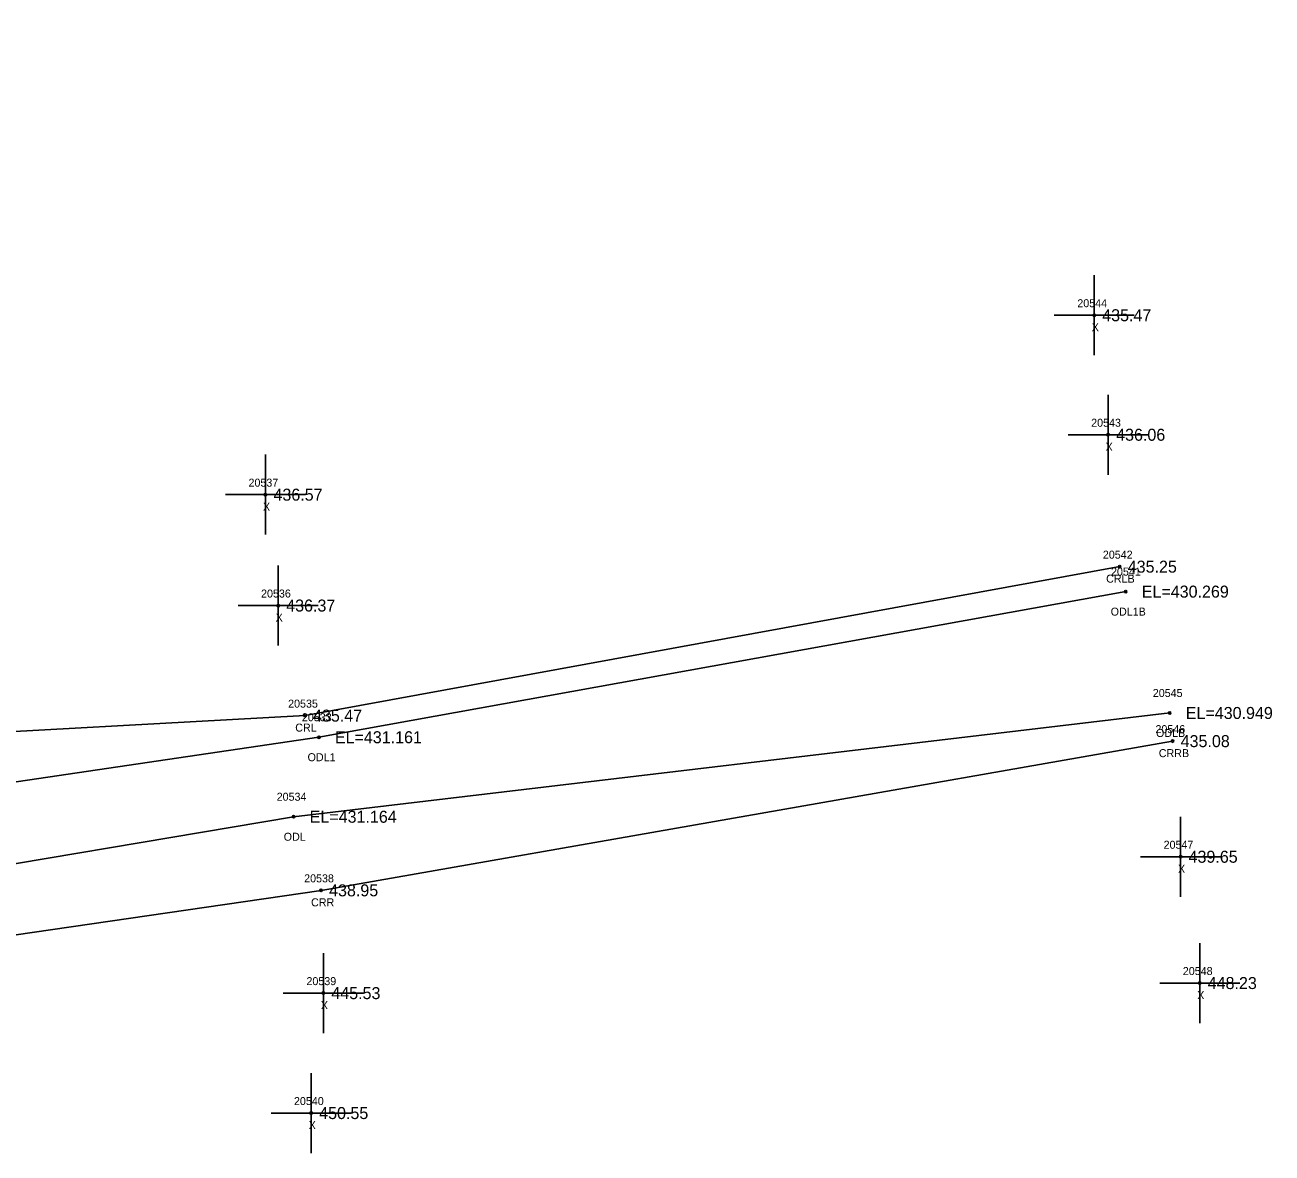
# Model space of a CAD drawing. Extents: x 1763022 to 1764007, y 824123 to 825394.
# Drawn here: x 1763783.3 to 1763939.1, y 824530.8 to 824671.8 of the extents above; entities that cross this region are included whole.
import ezdxf

# ---------------------------------------------------------------- set-up
doc = ezdxf.new("R2010")
doc.units = 0
for name, color, linetype in [('RD_EX_H2O', 7, 'Continuous'), ('RD_EX_H2O_txCode', 7, 'Continuous'), ('RD_EX_Misc', 7, 'Continuous'), ('RD_EX_Misc_txCode', 7, 'Continuous'), ('RD_EX_TX_H2O_ELEV', 7, 'Continuous'), ('RD_EX_TX_Misc_ELEV', 7, 'Continuous'), ('RD_SMD_Locator', 7, 'Continuous')]:
    doc.layers.add(name, color=color, linetype=linetype)

msp = doc.modelspace()

# ---------------------------------------------------------------- linework, layer by layer
at = {"layer": 'RD_EX_H2O'}
for points in [[(1763496.79, 824812.85), (1763505.69, 824806.42), (1763507.16, 824805.23), (1763521.58, 824789.49), (1763543.54, 824765.51), (1763572.14, 824752.09), (1763662.42, 824704.48), (1763697.56, 824670.47), (1763707.93, 824630.76), (1763723.52, 824595.87), (1763766.82, 824582.67), (1763818.29, 824585.49), (1763920.08, 824604.11)], [(1763494.44, 824810.56), (1763519.46, 824787), (1763539.48, 824759.37), (1763565.01, 824743.23), (1763659.79, 824699.35), (1763693.94, 824667), (1763705.55, 824629.75), (1763723.44, 824593.51), (1763767.2, 824575.02), (1763820.02, 824582.79), (1763920.83, 824600.99)], [(1763486.08, 824799.65), (1763514.15, 824779.95), (1763533.52, 824748.31), (1763547.12, 824731.03), (1763648.42, 824679.07), (1763662.67, 824682.83), (1763683.5, 824662.48), (1763694.46, 824627.33), (1763694.82, 824601.41), (1763712.85, 824586.53), (1763766.86, 824564.42), (1763816.87, 824572.85), (1763926.33, 824585.82)], [(1763485.59, 824798.12), (1763510.28, 824776.41), (1763530.73, 824746.57), (1763546.51, 824728.76), (1763647.95, 824677.16), (1763661.46, 824680.21), (1763679.15, 824659.29), (1763688.38, 824626.34), (1763689.04, 824599.45), (1763710.73, 824574.27), (1763740.3, 824562), (1763762.69, 824555.26), (1763820.3, 824563.65), (1763926.69, 824582.3)]]:
    msp.add_lwpolyline(points, dxfattribs=at)
at = {"layer": 'RD_EX_Misc'}
for p, q in [((1763916.89, 824630.54), (1763916.89, 824640.54)), ((1763911.89, 824635.54), (1763921.89, 824635.54)), ((1763918.63, 824615.6), (1763918.63, 824625.6)), ((1763913.63, 824620.6), (1763923.63, 824620.6)), ((1763813.35, 824608.11), (1763813.35, 824618.11)), ((1763808.35, 824613.11), (1763818.35, 824613.11)), ((1763814.94, 824594.25), (1763814.94, 824604.25)), ((1763809.94, 824599.25), (1763819.94, 824599.25)), ((1763927.68, 824562.85), (1763927.68, 824572.85)), ((1763922.68, 824567.85), (1763932.68, 824567.85)), ((1763930.07, 824547.06), (1763930.07, 824557.06)), ((1763820.58, 824545.8), (1763820.58, 824555.8)), ((1763925.07, 824552.06), (1763935.07, 824552.06)), ((1763815.58, 824550.8), (1763825.58, 824550.8)), ((1763819.06, 824530.81), (1763819.06, 824540.81)), ((1763814.06, 824535.81), (1763824.06, 824535.81))]:
    msp.add_line(p, q, dxfattribs=at)
at = {"layer": 'RD_SMD_Locator'}
for centre in [(1763916.89, 824635.54), (1763918.63, 824620.6), (1763813.35, 824613.11), (1763920.08, 824604.11), (1763920.83, 824600.99), (1763814.94, 824599.25), (1763818.29, 824585.49), (1763926.33, 824585.82), (1763820.02, 824582.79), (1763926.69, 824582.3), (1763816.87, 824572.85), (1763927.68, 824567.85), (1763820.3, 824563.65), (1763930.07, 824552.06), (1763820.58, 824550.8), (1763819.06, 824535.81)]:
    msp.add_circle(centre, 0.15, dxfattribs=at)

# ---------------------------------------------------------------- texts
at = {"layer": 'RD_EX_H2O_txCode'}
for s, p in [('20542', (1763917.97, 824605.11)), ('20541', (1763918.99, 824602.99)), ('CRLB', (1763918.38, 824602.11)), ('ODL1B', (1763918.95, 824597.99)), ('20545', (1763924.21, 824587.82)), ('20535', (1763816.18, 824586.49)), ('CRL', (1763817.07, 824583.49)), ('20533', (1763817.9, 824584.79)), ('20546', (1763924.54, 824583.3)), ('ODLB', (1763924.61, 824582.82)), ('ODL1', (1763818.61, 824579.79)), ('CRRB', (1763924.96, 824580.3)), ('20534', (1763814.75, 824574.85)), ('ODL', (1763815.63, 824569.85)), ('20538', (1763818.18, 824564.65)), ('CRR', (1763819.05, 824561.65))]:
    msp.add_text(s, height=1, dxfattribs=at).set_placement(p)
at = {"layer": 'RD_EX_Misc_txCode'}
for s, p in [('20544', (1763914.78, 824636.54)), ('X', (1763916.58, 824633.54)), ('20543', (1763916.51, 824621.6)), ('X', (1763918.31, 824618.6)), ('20537', (1763811.23, 824614.11)), ('X', (1763813.04, 824611.11)), ('20536', (1763812.8, 824600.25)), ('X', (1763814.62, 824597.25)), ('20547', (1763925.56, 824568.85)), ('X', (1763927.36, 824565.85)), ('20548', (1763927.96, 824553.06)), ('20539', (1763818.47, 824551.8)), ('X', (1763929.76, 824550.06)), ('X', (1763820.27, 824548.8)), ('20540', (1763816.91, 824536.81)), ('X', (1763818.75, 824533.81))]:
    msp.add_text(s, height=1, dxfattribs=at).set_placement(p)
at = {"layer": 'RD_EX_TX_H2O_ELEV'}
for s, p in [('435.25', (1763921.08, 824603.36)), ('EL=430.269', (1763922.83, 824600.24)), ('435.47', (1763819.29, 824584.74)), ('EL=430.949', (1763928.33, 824585.07)), ('EL=431.161', (1763822.02, 824582.04)), ('435.08', (1763927.69, 824581.55)), ('EL=431.164', (1763818.87, 824572.1)), ('438.95', (1763821.3, 824562.9))]:
    msp.add_text(s, height=1.5, dxfattribs=at).set_placement(p)
at = {"layer": 'RD_EX_TX_Misc_ELEV'}
for s, p in [('435.47', (1763917.89, 824634.79)), ('436.06', (1763919.63, 824619.85)), ('436.57', (1763814.35, 824612.36)), ('436.37', (1763815.94, 824598.5)), ('439.65', (1763928.68, 824567.1)), ('448.23', (1763931.07, 824551.31)), ('445.53', (1763821.58, 824550.05)), ('450.55', (1763820.06, 824535.06))]:
    msp.add_text(s, height=1.5, dxfattribs=at).set_placement(p)

doc.saveas('drawing.dxf')
